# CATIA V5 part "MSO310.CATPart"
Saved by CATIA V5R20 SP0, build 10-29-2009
Part number: MSO310
Definition: NONE
Nomenclature: MSO310
Source: Unknown
Description: MSO310
Bounding box of the stored display mesh (mm): x 0 to 12, y -5 to 5, z -5 to 5
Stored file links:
  C:\Users\Utente\Desktop\IO LAVORO\3D X SITO CF\X SITO\PLASTICA\CFMR\MSO310.CATPart
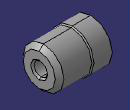
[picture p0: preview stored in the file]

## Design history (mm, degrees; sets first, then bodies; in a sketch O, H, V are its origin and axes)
Body1 "MSO310" (main body)
  Solid1: solid without history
